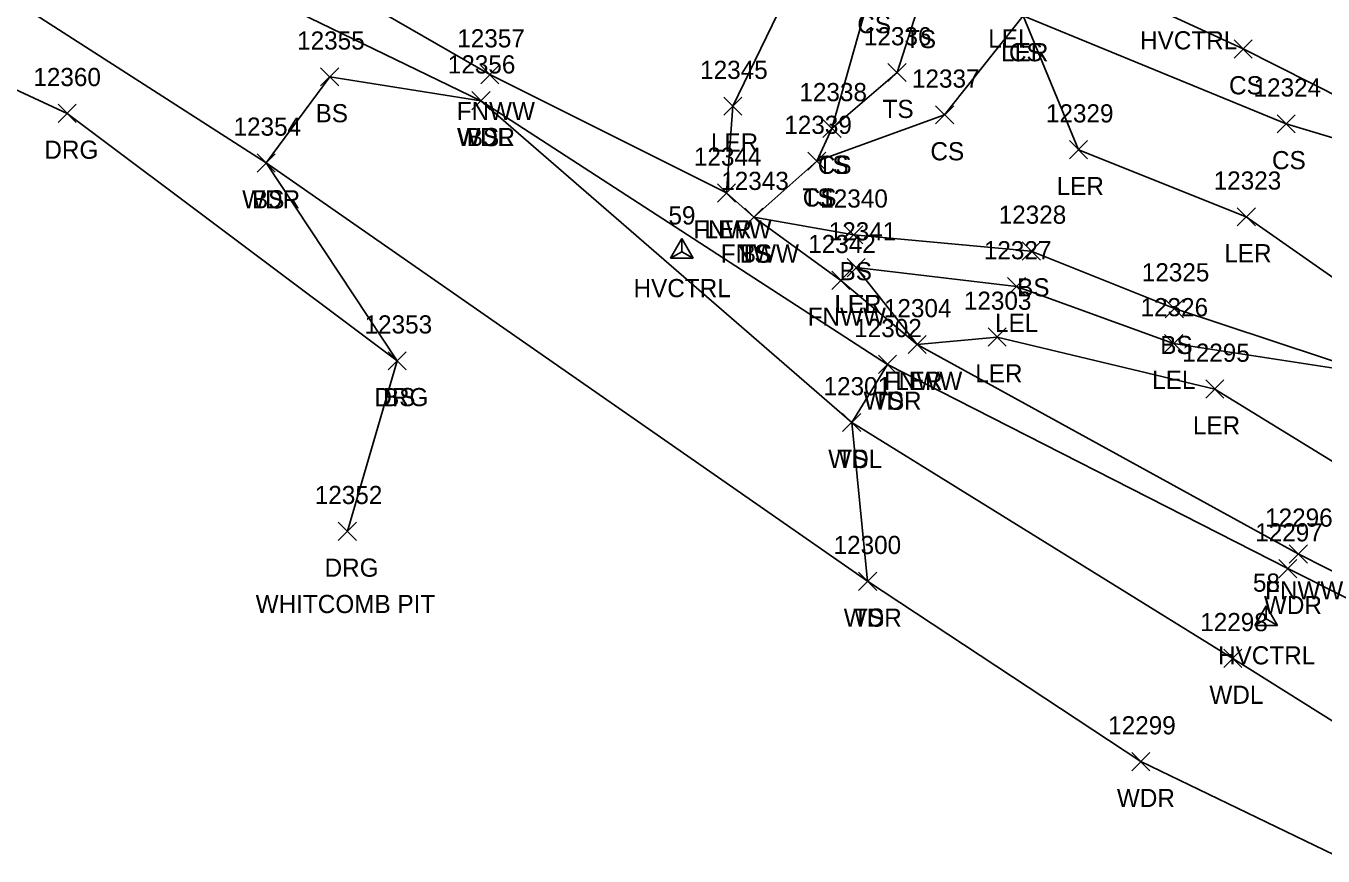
# Model space of a CAD drawing. Extents: x 1462089 to 1464015, y 730534 to 736144.
# Drawn here: x 1462216.4 to 1462359.2, y 731661.5 to 731752.9 of the extents above; entities that cross this region are included whole.
import ezdxf

# ---------------------------------------------------------------- set-up
doc = ezdxf.new("R2010")
doc.units = 0
for name, color, linetype in [('C_A', 7, 'Continuous'), ('C_I', 7, 'Continuous'), ('CPSM', 7, 'Continuous'), ('L_A', 7, 'Continuous'), ('L_I', 7, 'Continuous'), ('L_TIC', 7, 'Continuous'), ('LARO', 7, 'Continuous'), ('LAWA', 7, 'Continuous'), ('LELB', 7, 'Continuous'), ('LFNC', 7, 'Continuous'), ('R_A', 7, 'Continuous'), ('R_C', 7, 'Continuous'), ('R_I', 7, 'Continuous'), ('R_TIC', 7, 'Continuous'), ('RDG', 7, 'Continuous')]:
    doc.layers.add(name, color=color, linetype=linetype)

msp = doc.modelspace()

# ---------------------------------------------------------------- linework, layer by layer
at = {"layer": 'CPSM'}
for p, q in [((1462287.36, 731727.28), (1462288.61, 731729.45)), ((1462289.86, 731727.28), (1462288.61, 731729.45)), ((1462288.61, 731728), (1462288.61, 731729.45)), ((1462287.36, 731727.28), (1462288.61, 731728)), ((1462288.61, 731728), (1462288.61, 731728)), ((1462288.61, 731728), (1462289.86, 731727.28)), ((1462287.36, 731727.28), (1462289.86, 731727.28)), ((1462351.67, 731686.86), (1462352.92, 731689.03)), ((1462354.17, 731686.86), (1462352.92, 731689.03)), ((1462352.93, 731687.58), (1462352.92, 731689.03)), ((1462351.67, 731686.86), (1462352.93, 731687.58)), ((1462352.93, 731687.58), (1462352.93, 731687.58)), ((1462352.93, 731687.58), (1462354.17, 731686.86)), ((1462351.67, 731686.86), (1462354.17, 731686.86))]:
    msp.add_line(p, q, dxfattribs=at)
at = {"layer": 'L_TIC'}
for points in [[(1462349.38, 731749.32), (1462351.38, 731751.32)], [(1462351.38, 731749.32), (1462349.38, 731751.32)], [(1462311.3, 731746.72), (1462313.3, 731748.72)], [(1462313.3, 731746.72), (1462311.3, 731748.72)], [(1462248.87, 731746.25), (1462250.87, 731748.25)], [(1462250.87, 731746.25), (1462248.87, 731748.25)], [(1462266.49, 731746.49), (1462268.49, 731748.49)], [(1462268.49, 731746.49), (1462266.49, 731748.49)], [(1462265.51, 731743.62), (1462267.51, 731745.62)], [(1462267.51, 731743.62), (1462265.51, 731745.62)], [(1462265.51, 731743.62), (1462267.51, 731745.62)], [(1462267.51, 731743.62), (1462265.51, 731745.62)], [(1462265.51, 731743.62), (1462267.51, 731745.62)], [(1462267.51, 731743.62), (1462265.51, 731745.62)], [(1462293.22, 731743.02), (1462295.22, 731745.02)], [(1462295.22, 731743.02), (1462293.22, 731745.02)], [(1462316.53, 731742.06), (1462318.53, 731744.06)], [(1462318.53, 731742.06), (1462316.53, 731744.06)], [(1462354.12, 731741.08), (1462356.12, 731743.08)], [(1462356.12, 731741.08), (1462354.12, 731743.08)], [(1462304.14, 731740.57), (1462306.14, 731742.57)], [(1462306.14, 731740.57), (1462304.14, 731742.57)], [(1462304.14, 731740.57), (1462306.14, 731742.57)], [(1462306.14, 731740.57), (1462304.14, 731742.57)], [(1462331.27, 731738.23), (1462333.27, 731740.23)], [(1462333.27, 731738.23), (1462331.27, 731740.23)], [(1462241.87, 731736.77), (1462243.87, 731738.77)], [(1462243.87, 731736.77), (1462241.87, 731738.77)], [(1462241.87, 731736.77), (1462243.87, 731738.77)], [(1462243.87, 731736.77), (1462241.87, 731738.77)], [(1462302.48, 731736.97), (1462304.48, 731738.97)], [(1462304.48, 731736.97), (1462302.48, 731738.97)], [(1462302.48, 731736.97), (1462304.48, 731738.97)], [(1462304.48, 731736.97), (1462302.48, 731738.97)], [(1462292.53, 731733.47), (1462294.53, 731735.47)], [(1462294.53, 731733.47), (1462292.53, 731735.47)], [(1462292.53, 731733.47), (1462294.53, 731735.47)], [(1462294.53, 731733.47), (1462292.53, 731735.47)], [(1462295.54, 731730.8), (1462297.54, 731732.8)], [(1462297.54, 731730.8), (1462295.54, 731732.8)], [(1462295.54, 731730.8), (1462297.54, 731732.8)], [(1462297.54, 731730.8), (1462295.54, 731732.8)], [(1462295.54, 731730.8), (1462297.54, 731732.8)], [(1462297.54, 731730.8), (1462295.54, 731732.8)], [(1462349.73, 731730.84), (1462351.73, 731732.84)], [(1462351.73, 731730.84), (1462349.73, 731732.84)], [(1462306.53, 731728.86), (1462308.53, 731730.86)], [(1462308.53, 731728.86), (1462306.53, 731730.86)], [(1462326.07, 731727.08), (1462328.07, 731729.08)], [(1462328.07, 731727.08), (1462326.07, 731729.08)], [(1462306.8, 731725.25), (1462308.8, 731727.25)], [(1462308.8, 731725.25), (1462306.8, 731727.25)], [(1462306.8, 731725.25), (1462308.8, 731727.25)], [(1462308.8, 731725.25), (1462306.8, 731727.25)], [(1462305.11, 731723.85), (1462307.11, 731725.85)], [(1462307.11, 731723.85), (1462305.11, 731725.85)], [(1462324.44, 731723.17), (1462326.44, 731725.17)], [(1462326.44, 731723.17), (1462324.44, 731725.17)], [(1462341.82, 731720.74), (1462343.82, 731722.74)], [(1462343.82, 731720.74), (1462341.82, 731722.74)], [(1462313.52, 731716.79), (1462315.52, 731718.79)], [(1462315.52, 731716.79), (1462313.52, 731718.79)], [(1462313.52, 731716.79), (1462315.52, 731718.79)], [(1462315.52, 731716.79), (1462313.52, 731718.79)], [(1462322.32, 731717.61), (1462324.32, 731719.61)], [(1462324.32, 731717.61), (1462322.32, 731719.61)], [(1462341.73, 731716.9), (1462343.73, 731718.9)], [(1462343.73, 731716.9), (1462341.73, 731718.9)], [(1462256.29, 731715), (1462258.29, 731717)], [(1462258.29, 731715), (1462256.29, 731717)], [(1462310.25, 731714.6), (1462312.25, 731716.6)], [(1462312.25, 731714.6), (1462310.25, 731716.6)], [(1462310.25, 731714.6), (1462312.25, 731716.6)], [(1462312.25, 731714.6), (1462310.25, 731716.6)], [(1462346.27, 731711.89), (1462348.27, 731713.89)], [(1462348.27, 731711.89), (1462346.27, 731713.89)], [(1462306.31, 731708.2), (1462308.31, 731710.2)], [(1462308.31, 731708.2), (1462306.31, 731710.2)], [(1462306.31, 731708.2), (1462308.31, 731710.2)], [(1462308.31, 731708.2), (1462306.31, 731710.2)], [(1462355.45, 731693.74), (1462357.45, 731695.74)], [(1462357.45, 731693.74), (1462355.45, 731695.74)], [(1462354.3, 731692.12), (1462356.3, 731694.12)], [(1462356.3, 731692.12), (1462354.3, 731694.12)], [(1462308.06, 731690.73), (1462310.06, 731692.73)], [(1462310.06, 731690.73), (1462308.06, 731692.73)], [(1462308.06, 731690.73), (1462310.06, 731692.73)], [(1462310.06, 731690.73), (1462308.06, 731692.73)], [(1462348.25, 731682.24), (1462350.25, 731684.24)], [(1462350.25, 731682.24), (1462348.25, 731684.24)], [(1462338.13, 731670.88), (1462340.13, 731672.88)], [(1462340.13, 731670.88), (1462338.13, 731672.88)]]:
    msp.add_lwpolyline(points, dxfattribs=at)
at = {"layer": 'LARO'}
for points in [[(1462293.53, 731734.47), (1462294.22, 731744.02), (1462301.63, 731759.31)], [(1462378.85, 731730.19), (1462367.33, 731720.21), (1462350.73, 731731.84), (1462332.27, 731739.23), (1462326.17, 731753.96)], [(1462393.44, 731685.6), (1462386.6, 731694.14), (1462373.48, 731696.75), (1462347.27, 731712.89), (1462323.32, 731718.61), (1462314.52, 731717.79), (1462307.8, 731726.25)], [(1462398.02, 731703.24), (1462387.75, 731705.26), (1462382.83, 731707.65), (1462378.91, 731710.74), (1462364.65, 731714.51), (1462342.73, 731717.9), (1462325.44, 731724.17), (1462307.8, 731726.25)]]:
    msp.add_lwpolyline(points, dxfattribs=at)
at = {"layer": 'LAWA'}
for points in [[(1462397.71, 731569.75), (1462407.25, 731591.59), (1462407.12, 731591.77), (1462391.91, 731630.11), (1462376.36, 731653.92), (1462339.13, 731671.88), (1462309.06, 731691.73), (1462242.87, 731737.77), (1462189.26, 731772.23), (1462179.25, 731777.64), (1462155.87, 731796.25), (1462116.88, 731817.84), (1462092.33, 731845.64)], [(1462378.23, 731455.67), (1462393.54, 731485.05), (1462397.88, 731504.85), (1462412.43, 731541.74), (1462426.97, 731578.82), (1462435.48, 731600.22), (1462426.04, 731605), (1462419.39, 731620.93), (1462398.1, 731641.67), (1462386.95, 731659.57), (1462349.25, 731683.24), (1462307.31, 731709.2), (1462266.51, 731744.62)], [(1462529.31, 731609.09), (1462503.69, 731615.3), (1462482.96, 731621.76), (1462463.28, 731631.86), (1462443.06, 731640.91), (1462419.39, 731655.59), (1462381.11, 731680.15), (1462355.3, 731693.12), (1462311.25, 731715.6), (1462266.51, 731744.62)]]:
    msp.add_lwpolyline(points, dxfattribs=at)
at = {"layer": 'LELB'}
for points in [[(1462188.49, 731840.6), (1462212.54, 731825.16), (1462231.64, 731814.23), (1462269.15, 731796.29), (1462295.64, 731781.88), (1462315.16, 731776.86), (1462323.76, 731770.87), (1462330.76, 731759.39), (1462350.38, 731750.32), (1462369.06, 731740.92)], [(1462257.29, 731716), (1462242.87, 731737.77), (1462249.87, 731747.25), (1462266.51, 731744.62), (1462234.77, 731760.03), (1462195.44, 731782.12), (1462183.53, 731790.84), (1462179.25, 731777.64)], [(1462310.12, 731770.19), (1462309.48, 731757.05), (1462305.14, 731741.57)], [(1462314.97, 731767.91), (1462314.76, 731755.41), (1462312.3, 731747.72), (1462305.14, 731741.57), (1462303.48, 731737.97), (1462296.54, 731731.8)], [(1462378.85, 731730.19), (1462368.57, 731738.03), (1462355.12, 731742.08), (1462326.17, 731753.96), (1462317.53, 731743.06), (1462303.48, 731737.97)], [(1462398.9, 731700.85), (1462396.21, 731692.4), (1462387.19, 731697.16), (1462377.15, 731702.63), (1462364.65, 731714.51), (1462342.82, 731721.74), (1462327.07, 731728.08), (1462307.53, 731729.86), (1462296.54, 731731.8)], [(1462309.06, 731691.73), (1462307.31, 731709.2), (1462311.25, 731715.6)]]:
    msp.add_lwpolyline(points, dxfattribs=at)
at = {"layer": 'LFNC'}
msp.add_lwpolyline([(1462485.04, 731625.17), (1462466.86, 731635.35), (1462445.59, 731646.34), (1462441.06, 731648.62), (1462421.59, 731659.28), (1462381.96, 731681.83), (1462356.45, 731694.74), (1462314.52, 731717.79), (1462306.11, 731724.85), (1462296.54, 731731.8), (1462293.53, 731734.47), (1462267.49, 731747.49), (1462237.87, 731764.56), (1462196.32, 731787.42), (1462159.85, 731807.27), (1462122.39, 731829.3), (1462092.33, 731845.64)], dxfattribs=at)
at = {"layer": 'R_TIC'}
for points in [[(1462219.97, 731742.23), (1462221.97, 731744.23)], [(1462221.97, 731742.23), (1462219.97, 731744.23)], [(1462256.29, 731715), (1462258.29, 731717)], [(1462258.29, 731715), (1462256.29, 731717)], [(1462250.81, 731696.23), (1462252.81, 731698.23)], [(1462252.81, 731696.23), (1462250.81, 731698.23)]]:
    msp.add_lwpolyline(points, dxfattribs=at)
at = {"layer": 'RDG'}
msp.add_lwpolyline([(1462251.81, 731697.23), (1462257.29, 731716), (1462220.97, 731743.23), (1462202.71, 731751.69), (1462188.31, 731760.15)], dxfattribs=at)

# ---------------------------------------------------------------- texts
at = {"layer": 'C_A'}
for p in [(1462339.04, 731750.27), (1462283.3, 731723), (1462347.62, 731682.58)]:
    msp.add_text('HVCTRL', height=2, dxfattribs=at).set_placement(p)
at = {"layer": 'C_I'}
for s, p in [('59', (1462287.14, 731731)), ('58', (1462351.46, 731690.58))]:
    msp.add_text(s, height=2, dxfattribs=at).set_placement(p)
at = {"layer": 'L_A'}
for s, p in [('CS', (1462307.92, 731752.05)), ('TS', (1462313.17, 731750.41)), ('LEL', (1462322.33, 731750.47)), ('LER', (1462323.75, 731748.96)), ('CS', (1462324.61, 731748.96)), ('CS', (1462348.83, 731745.32)), ('FNWW', (1462263.84, 731742.49)), ('TS', (1462310.71, 731742.72)), ('BS', (1462248.31, 731742.25)), ('WDR', (1462263.87, 731739.62)), ('WDL', (1462263.93, 731739.62)), ('BS', (1462264.95, 731739.62)), ('LER', (1462291.81, 731739.02)), ('CS', (1462315.97, 731738.06)), ('CS', (1462353.56, 731737.08)), ('TS', (1462303.55, 731736.57)), ('CS', (1462303.58, 731736.57)), ('LER', (1462329.86, 731734.23)), ('WDR', (1462240.23, 731732.77)), ('BS', (1462241.31, 731732.77)), ('TS', (1462301.89, 731732.97)), ('CS', (1462301.92, 731732.97)), ('FNWW', (1462289.88, 731729.47)), ('LER', (1462291.11, 731729.47)), ('FNWW', (1462292.89, 731726.8)), ('TS', (1462294.95, 731726.8)), ('BS', (1462294.99, 731726.8)), ('LER', (1462348.31, 731726.84)), ('BS', (1462305.97, 731724.86)), ('BS', (1462325.51, 731723.08)), ('LER', (1462305.38, 731721.25)), ('LEL', (1462305.44, 731721.25)), ('FNWW', (1462302.46, 731719.85)), ('LEL', (1462323.08, 731719.17)), ('BS', (1462341.26, 731716.74)), ('FNWW', (1462310.86, 731712.79)), ('LER', (1462312.1, 731712.79)), ('LER', (1462320.9, 731713.61)), ('LEL', (1462340.37, 731712.9)), ('BS', (1462255.73, 731711)), ('WDR', (1462308.61, 731710.6)), ('TS', (1462309.66, 731710.6)), ('LER', (1462344.85, 731707.89)), ('WDL', (1462304.73, 731704.2)), ('TS', (1462305.72, 731704.2)), ('FNWW', (1462352.79, 731689.74)), ('TS', (1462307.47, 731686.73)), ('WDR', (1462352.67, 731688.12)), ('WDR', (1462306.43, 731686.73)), ('WDL', (1462346.67, 731678.24)), ('WDR', (1462336.49, 731666.88))]:
    msp.add_text(s, height=2, dxfattribs=at).set_placement(p)
at = {"layer": 'L_I'}
for s, p in [('12355', (1462246.28, 731750.25)), ('12357', (1462263.9, 731750.49)), ('12336', (1462308.65, 731750.72)), ('12356', (1462262.86, 731747.62)), ('12356', (1462262.86, 731747.62)), ('12356', (1462262.86, 731747.62)), ('12345', (1462290.63, 731747.02)), ('12337', (1462313.94, 731746.06)), ('12338', (1462301.55, 731744.57)), ('12338', (1462301.55, 731744.57)), ('12324', (1462351.53, 731745.08)), ('12339', (1462299.89, 731740.97)), ('12339', (1462299.89, 731740.97)), ('12329', (1462328.68, 731742.23)), ('12354', (1462239.28, 731740.77)), ('12354', (1462239.28, 731740.77)), ('12344', (1462289.94, 731737.47)), ('12344', (1462289.94, 731737.47)), ('12343', (1462292.95, 731734.8)), ('12343', (1462292.95, 731734.8)), ('12343', (1462292.95, 731734.8)), ('12323', (1462347.14, 731734.84)), ('12340', (1462303.85, 731732.86)), ('12328', (1462323.48, 731731.08)), ('12341', (1462304.78, 731729.25)), ('12341', (1462304.78, 731729.25)), ('12342', (1462302.52, 731727.85)), ('12327', (1462321.85, 731727.17)), ('12325', (1462339.23, 731724.74)), ('12303', (1462319.65, 731721.61)), ('12304', (1462310.85, 731720.79)), ('12304', (1462310.85, 731720.79)), ('12326', (1462339.09, 731720.9)), ('12353', (1462253.7, 731719)), ('12302', (1462307.58, 731718.6)), ('12302', (1462307.58, 731718.6)), ('12295', (1462343.68, 731715.89)), ('12301', (1462304.21, 731712.2)), ('12301', (1462304.21, 731712.2)), ('12296', (1462352.8, 731697.74)), ('12297', (1462351.71, 731696.12)), ('12300', (1462305.31, 731694.73)), ('12300', (1462305.31, 731694.73)), ('12298', (1462345.66, 731686.24)), ('12299', (1462335.53, 731674.88))]:
    msp.add_text(s, height=2, dxfattribs=at).set_placement(p)
at = {"layer": 'R_A'}
for p in [(1462218.46, 731738.23), (1462254.78, 731711), (1462249.3, 731692.23)]:
    msp.add_text('DRG', height=2, dxfattribs=at).set_placement(p)
at = {"layer": 'R_C'}
msp.add_text('WHITCOMB PIT', height=2, dxfattribs=at).set_placement((1462241.72, 731688.23))
at = {"layer": 'R_I'}
for s, p in [('12360', (1462217.25, 731746.23)), ('12353', (1462253.7, 731719)), ('12352', (1462248.22, 731700.23))]:
    msp.add_text(s, height=2, dxfattribs=at).set_placement(p)

doc.saveas('drawing.dxf')
